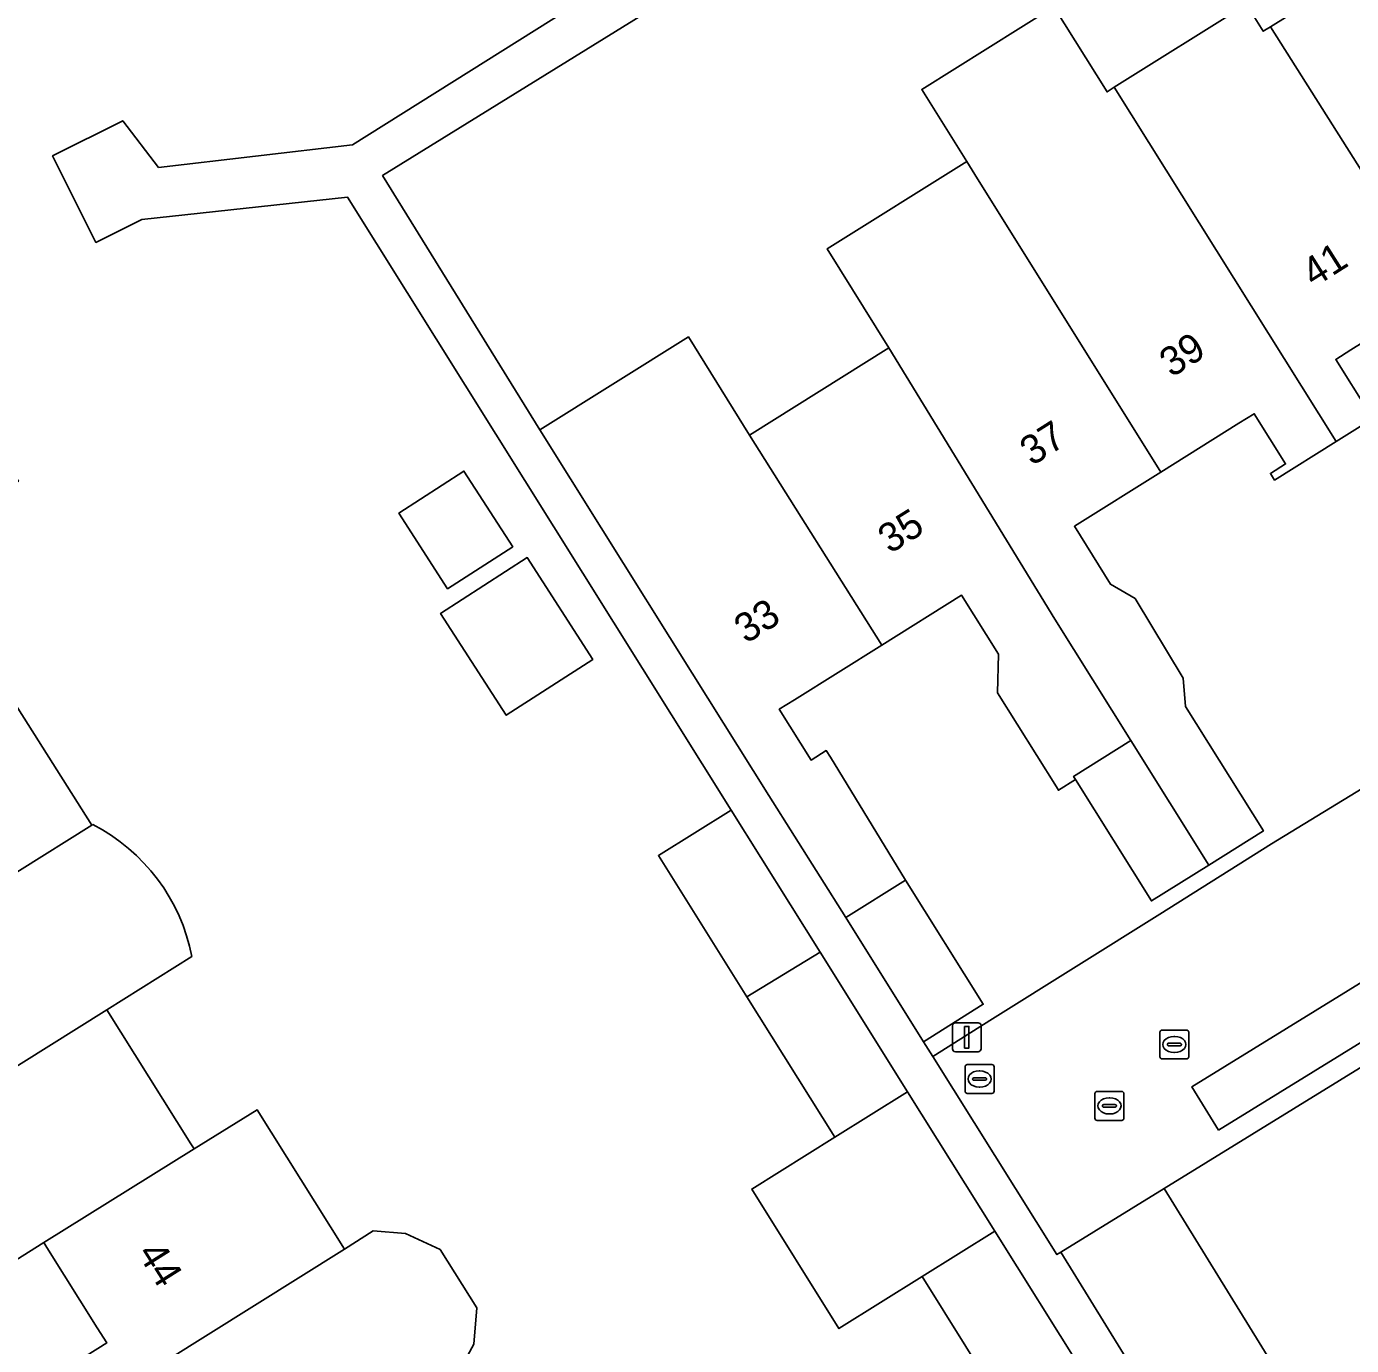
# Model space of a CAD drawing. Extents: x 157767 to 159172, y 387839 to 389425.
# Drawn here: x 158299.66 to 158345.52, y 388177.16 to 388222.82 of the extents above; entities that cross this region are included whole.
import ezdxf

# ---------------------------------------------------------------- set-up
doc = ezdxf.new("R2010")
doc.units = 0
for name, color, linetype in [('IMGEO_Brandkraan', 7, 'Continuous'), ('IMGEO_Erf', 7, 'Continuous'), ('IMGEO_Kolk', 7, 'Continuous'), ('IMGEO_Lichtmast', 7, 'Continuous'), ('IMGEO_Muur', 7, 'Continuous'), ('IMGEO_Pand', 7, 'Continuous'), ('IMGEO_Pand_nummerreeks', 7, 'Continuous'), ('IMGEO_Parkeervlak_open', 7, 'Continuous'), ('IMGEO_Rijbaan_lokaal_open', 7, 'Continuous'), ('IMGEO_Rioolput', 7, 'Continuous'), ('IMGEO_Voetpad_open', 7, 'Continuous')]:
    doc.layers.add(name, color=color, linetype=linetype)

msp = doc.modelspace()

# ---------------------------------------------------------------- linework, layer by layer
at = {"layer": 'IMGEO_Brandkraan'}
for p, q in [((158332.146, 388185.961), (158332.146, 388186.813)), ((158332.221, 388186.887), (158333.073, 388186.887)), ((158332.634, 388186.667), (158332.659, 388186.667)), ((158333.147, 388186.813), (158333.147, 388185.961)), ((158332.405, 388186.381), (158332.405, 388186.393)), ((158332.843, 388186.344), (158332.445, 388186.344)), ((158332.448, 388186.43), (158332.846, 388186.43)), ((158332.889, 388186.393), (158332.889, 388186.381)), ((158333.073, 388185.887), (158332.221, 388185.887)), ((158332.657, 388186.107), (158332.632, 388186.107))]:
    msp.add_line(p, q, dxfattribs=at)
for points in [[(158332.146, 388185.961), (158332.146, 388186.813)], [(158332.221, 388186.887), (158333.073, 388186.887)], [(158333.147, 388186.813), (158333.147, 388185.961)], [(158333.073, 388185.887), (158332.221, 388185.887)]]:
    msp.add_lwpolyline(points, dxfattribs=at)
for centre, radius, start, end in [((158332.223, 388186.811), 0.0765, 91.552, 178.448), ((158332.223, 388186.811), 0.0765, 91.552, 178.448), ((158333.071, 388186.811), 0.0765, 1.552, 88.448), ((158333.071, 388186.811), 0.0765, 1.552, 88.448), ((158332.445, 388186.39), 0.0403, 85.8775, 175.7526), ((158332.442, 388186.38), 0.0366, 178.938, 274.7102), ((158332.846, 388186.387), 0.043, 264.8664, 352.4533), ((158332.85, 388186.392), 0.0386, 1.7309, 96.639), ((158332.223, 388185.963), 0.0765, 181.552, 268.448), ((158332.223, 388185.963), 0.0765, 181.552, 268.448), ((158333.071, 388185.963), 0.0765, 271.552, 358.448), ((158333.071, 388185.963), 0.0765, 271.552, 358.448)]:
    msp.add_arc(centre, radius, start, end, dxfattribs=at)
for centre, major_axis, ratio, start_param, end_param in [((158332.633, 388186.387), (-0.387, 0.002), 0.722429, 4.712389, 7.853982), ((158332.658, 388186.387), (-0.39, 0.002), 0.717154, 1.570796, 4.712389)]:
    msp.add_ellipse(centre, major_axis=major_axis, ratio=ratio, start_param=start_param, end_param=end_param, dxfattribs=at)
at = {"layer": 'IMGEO_Erf'}
for points in [[(158352.638, 388149.483), (158342.348, 388166.462), (158339.829, 388164.885), (158336.71, 388169.869), (158333.687, 388174.698), (158330.654, 388179.545), (158327.78, 388177.748), (158324.761, 388182.578), (158327.632, 388184.373), (158324.594, 388189.227), (158321.531, 388194.121), (158324.05, 388195.698), (158310.772, 388216.911), (158303.653, 388216.141), (158302.062, 388215.346), (158300.563, 388218.345), (158302.989, 388219.558), (158304.231, 388217.941), (158310.937, 388218.725), (158339.805, 388236.853), (158338.261, 388239.455), (158339.941, 388240.451), (158341.485, 388237.85), (158354.972, 388246.308)], [(158352.633, 388242.812), (158311.985, 388217.662), (158317.43, 388208.862), (158322.569, 388212.076), (158324.68, 388208.678), (158329.51, 388211.699), (158327.369, 388215.123), (158332.203, 388218.146), (158330.642, 388220.645), (158335.214, 388223.501), (158337.058, 388220.56), (158337.309, 388220.717), (158341.89, 388223.582), (158342.466, 388222.66), (158342.715, 388222.816), (158347.548, 388225.838)], [(158288.882, 388228.585), (158287.241, 388221.328), (158285.582, 388213.989), (158285.537, 388213.792), (158285.678, 388213.567), (158287.513, 388214.764), (158290.986, 388215.147), (158292.361, 388212.95), (158293.959, 388210.397), (158296.356, 388211.9), (158299.38, 388207.078), (158296.984, 388205.563), (158295.817, 388204.825), (158298.865, 388200.005), (158301.921, 388195.173), (158301.957, 388195.196)], [(158348.581, 388213.55), (158345.5, 388211.624), (158344.976, 388211.296), (158346.113, 388209.477)], [(158346.781, 388209.576), (158344.993, 388208.458), (158342.854, 388207.12), (158342.711, 388207.349), (158343.237, 388207.678), (158342.15, 388209.416), (158341.624, 388209.087), (158338.92, 388207.396), (158335.927, 388205.524), (158337.182, 388203.516), (158338.026, 388203.018), (158339.693, 388200.264), (158339.772, 388199.287), (158342.47, 388194.973), (158340.58, 388193.791), (158338.596, 388192.55), (158335.966, 388196.755), (158335.373, 388196.384), (158335.303, 388196.496), (158333.262, 388199.758), (158333.301, 388201.09), (158332.025, 388203.131), (158329.261, 388201.403), (158326.24, 388199.514), (158325.715, 388199.186), (158326.814, 388197.429), (158327.339, 388197.757), (158327.482, 388197.528), (158330.086, 388193.272), (158332.774, 388188.973), (158330.703, 388187.677), (158331.025, 388187.169), (158333.092, 388188.466), (158338.88, 388192.098), (158342.746, 388194.533), (158348.606, 388198.107)], [(158305.387, 388190.624), (158302.443, 388188.781), (158305.35, 388184.137), (158305.458, 388183.964), (158307.641, 388185.324), (158310.661, 388180.499), (158311.663, 388181.126), (158312.771, 388181.044), (158313.976, 388180.48), (158315.241, 388178.461), (158315.14, 388177.208), (158314.617, 388176.244)], [(158300.695, 388176.163), (158302.435, 388177.252), (158302.107, 388177.777), (158300.366, 388180.558), (158300.261, 388180.726), (158298.305, 388179.507)]]:
    msp.add_lwpolyline(points, dxfattribs=at)
for points in [[(158312.546, 388205.978), (158314.8, 388207.43), (158316.488, 388204.812), (158314.234, 388203.359)], [(158316.261, 388198.98), (158313.991, 388202.504), (158316.989, 388204.436), (158319.259, 388200.912)], [(158365.167, 388198.706), (158352.615, 388190.965), (158339.034, 388182.597), (158342.746, 388176.574), (158344.937, 388173.02), (158341.361, 388170.817), (158342.735, 388168.588), (158345.292, 388170.164), (158347.446, 388166.668), (158349.073, 388167.671), (158351.12, 388164.35), (158349.493, 388163.347), (158350.241, 388162.135), (158353.069, 388157.546), (158355.265, 388158.899), (158357.294, 388155.608), (158355.098, 388154.254), (158355.258, 388153.995), (158352.825, 388152.496), (158354.129, 388150.416), (158383.764, 388168.963), (158383.379, 388169.579), (158381.815, 388172.081)]]:
    msp.add_lwpolyline(points, close=True, dxfattribs=at)
msp.add_arc((158298.947, 388189.365), 6.562, 11.0598, 62.6961, dxfattribs=at)
at = {"layer": 'IMGEO_Kolk'}
for p, q in [((158338.887, 388187.156), (158338.887, 388188.008)), ((158338.962, 388188.082), (158339.814, 388188.082)), ((158339.888, 388188.008), (158339.888, 388187.156)), ((158339.146, 388187.576), (158339.146, 388187.588)), ((158339.584, 388187.539), (158339.186, 388187.539)), ((158339.189, 388187.625), (158339.587, 388187.625)), ((158339.375, 388187.862), (158339.4, 388187.862)), ((158339.63, 388187.588), (158339.63, 388187.576)), ((158339.814, 388187.082), (158338.962, 388187.082)), ((158339.398, 388187.302), (158339.373, 388187.302))]:
    msp.add_line(p, q, dxfattribs=at)
for points in [[(158338.887, 388187.156), (158338.887, 388188.008)], [(158338.962, 388188.082), (158339.814, 388188.082)], [(158339.888, 388188.008), (158339.888, 388187.156)], [(158339.814, 388187.082), (158338.962, 388187.082)]]:
    msp.add_lwpolyline(points, dxfattribs=at)
for centre, radius, start, end in [((158338.964, 388188.006), 0.0765, 91.552, 178.448), ((158338.964, 388188.006), 0.0765, 91.552, 178.448), ((158339.812, 388188.006), 0.0765, 1.552, 88.448), ((158339.812, 388188.006), 0.0765, 1.552, 88.448), ((158339.186, 388187.585), 0.0403, 85.8775, 175.7526), ((158339.183, 388187.575), 0.0366, 178.938, 274.7102), ((158339.587, 388187.582), 0.043, 264.8664, 352.4533), ((158339.591, 388187.587), 0.0386, 1.7309, 96.639), ((158338.964, 388187.158), 0.0765, 181.552, 268.448), ((158338.964, 388187.158), 0.0765, 181.552, 268.448), ((158339.812, 388187.158), 0.0765, 271.552, 358.448), ((158339.812, 388187.158), 0.0765, 271.552, 358.448)]:
    msp.add_arc(centre, radius, start, end, dxfattribs=at)
for centre, major_axis, ratio, start_param, end_param in [((158339.374, 388187.582), (-0.387, 0.002), 0.722429, 4.712389, 7.853982), ((158339.399, 388187.582), (-0.39, 0.002), 0.717154, 1.570796, 4.712389)]:
    msp.add_ellipse(centre, major_axis=major_axis, ratio=ratio, start_param=start_param, end_param=end_param, dxfattribs=at)
at = {"layer": 'IMGEO_Lichtmast'}
for p, q in [((158331.708, 388187.433), (158331.708, 388188.233)), ((158331.708, 388188.233), (158331.708, 388187.433)), ((158331.808, 388188.333), (158332.598, 388188.333)), ((158332.598, 388188.333), (158331.808, 388188.333)), ((158332.698, 388188.233), (158332.698, 388187.433)), ((158332.698, 388187.433), (158332.698, 388188.233)), ((158332.598, 388187.333), (158331.808, 388187.333)), ((158331.808, 388187.333), (158332.598, 388187.333))]:
    msp.add_line(p, q, dxfattribs=at)
msp.add_lwpolyline([(158332.128, 388188.208), (158332.278, 388188.208), (158332.278, 388187.458), (158332.128, 388187.458), (158332.128, 388188.208)], dxfattribs=at)
for centre, start, end in [((158331.808, 388188.233), 90, 180), ((158331.808, 388188.233), 90, 180), ((158332.598, 388188.233), 0, 90), ((158332.598, 388188.233), 360, 90), ((158331.808, 388187.433), 180, 270), ((158331.808, 388187.433), 180, 270), ((158332.598, 388187.433), 270, 0), ((158332.598, 388187.433), 270, 0)]:
    msp.add_arc(centre, 0.1, start, end, dxfattribs=at)
at = {"layer": 'IMGEO_Muur'}
msp.add_lwpolyline([(158352.615, 388190.965), (158339.034, 388182.597)], dxfattribs=at)
at = {"layer": 'IMGEO_Pand'}
for points in [[(158352.186, 388218.514), (158347.548, 388225.838), (158342.715, 388222.816), (158348.581, 388213.55), (158350.352, 388214.658), (158350.209, 388214.887), (158349.684, 388214.559), (158348.609, 388216.277), (158349.134, 388216.605)], [(158337.309, 388220.717), (158337.058, 388220.56), (158335.214, 388223.501), (158330.642, 388220.645), (158332.203, 388218.146), (158332.484, 388217.7), (158338.92, 388207.396), (158341.624, 388209.087), (158342.15, 388209.416), (158343.237, 388207.678), (158342.711, 388207.349), (158342.854, 388207.12), (158344.993, 388208.458)], [(158337.309, 388220.717), (158344.993, 388208.458), (158346.781, 388209.576), (158346.638, 388209.805), (158346.113, 388209.477), (158344.976, 388211.296), (158345.5, 388211.624), (158348.581, 388213.55), (158342.715, 388222.816), (158342.466, 388222.66), (158341.89, 388223.582)], [(158338.92, 388207.396), (158332.484, 388217.7), (158332.203, 388218.146), (158327.369, 388215.123), (158329.51, 388211.699), (158335.252, 388202.31), (158337.882, 388198.105), (158340.58, 388193.791), (158342.47, 388194.973), (158339.772, 388199.287), (158339.693, 388200.264), (158338.026, 388203.018), (158337.182, 388203.516), (158335.927, 388205.524)], [(158328.015, 388191.977), (158330.086, 388193.272), (158327.482, 388197.528), (158327.339, 388197.757), (158326.814, 388197.429), (158325.715, 388199.186), (158326.24, 388199.514), (158329.261, 388201.403), (158324.68, 388208.678), (158322.569, 388212.076), (158317.43, 388208.862), (158319.551, 388205.471), (158322.7, 388200.436), (158325.351, 388196.196)], [(158324.68, 388208.678), (158329.261, 388201.403), (158332.025, 388203.131), (158333.301, 388201.09), (158333.262, 388199.758), (158335.303, 388196.496), (158335.373, 388196.384), (158335.966, 388196.755), (158335.898, 388196.864), (158337.882, 388198.105), (158335.252, 388202.31), (158329.51, 388211.699)], [(158316.488, 388204.812), (158314.8, 388207.43), (158312.546, 388205.978), (158314.234, 388203.359)], [(158319.259, 388200.912), (158316.989, 388204.436), (158313.991, 388202.504), (158316.261, 388198.98)], [(158299.421, 388193.609), (158301.921, 388195.173), (158298.865, 388200.005), (158296.392, 388198.45), (158282.82, 388189.919), (158283.973, 388188.076), (158288.449, 388190.878), (158288.121, 388191.404), (158289.916, 388192.527), (158290.245, 388192.002), (158292.107, 388189.027)], [(158335.966, 388196.755), (158338.596, 388192.55), (158340.58, 388193.791), (158337.882, 388198.105), (158335.898, 388196.864)], [(158327.127, 388190.782), (158324.05, 388195.698), (158321.531, 388194.121), (158324.594, 388189.227)], [(158328.015, 388191.977), (158330.703, 388187.677), (158332.774, 388188.973), (158330.086, 388193.272)], [(158330.152, 388185.948), (158327.127, 388190.782), (158324.594, 388189.227), (158327.632, 388184.373)], [(158305.458, 388183.964), (158305.35, 388184.137), (158302.443, 388188.781), (158288.839, 388180.263), (158290.058, 388178.315), (158294.534, 388181.117), (158294.206, 388181.643), (158295.961, 388182.741), (158296.29, 388182.216), (158298.183, 388179.192), (158298.412, 388179.335), (158298.305, 388179.507), (158300.261, 388180.726)], [(158330.152, 388185.948), (158327.632, 388184.373), (158324.761, 388182.578), (158327.78, 388177.748), (158330.654, 388179.545), (158333.174, 388181.121)], [(158310.661, 388180.499), (158307.641, 388185.324), (158305.458, 388183.964), (158300.261, 388180.726), (158300.366, 388180.558), (158302.107, 388177.777), (158302.435, 388177.252), (158300.695, 388176.163), (158300.366, 388176.687), (158300.137, 388176.544), (158301.323, 388174.65)], [(158342.746, 388176.574), (158339.034, 388182.597), (158335.458, 388180.394), (158339.187, 388174.344)], [(158313.689, 388175.662), (158314.617, 388176.244), (158315.14, 388177.208), (158315.241, 388178.461), (158313.976, 388180.48), (158312.771, 388181.044), (158311.663, 388181.126), (158310.661, 388180.499), (158301.323, 388174.65), (158302.563, 388172.668), (158302.792, 388172.812), (158302.464, 388173.338), (158304.215, 388174.434), (158304.546, 388173.91), (158306.343, 388171.059)], [(158333.174, 388181.121), (158330.654, 388179.545), (158333.687, 388174.698), (158336.208, 388176.272)]]:
    msp.add_lwpolyline(points, close=True, dxfattribs=at)
for points in [[(158301.957, 388195.196), (158301.921, 388195.173), (158299.421, 388193.609), (158292.107, 388189.027), (158293.851, 388186.24), (158294.18, 388185.715), (158292.367, 388184.581), (158292.038, 388185.106), (158287.562, 388182.304), (158288.839, 388180.263), (158302.443, 388188.781)], [(158302.443, 388188.781), (158305.387, 388190.624)]]:
    msp.add_lwpolyline(points, dxfattribs=at)
msp.add_arc((158298.947, 388189.365), 6.562, 11.0598, 62.6961, dxfattribs=at)
at = {"layer": 'IMGEO_Parkeervlak_open'}
msp.add_lwpolyline([(158340.911, 388184.618), (158361.412, 388197.254), (158360.492, 388198.747), (158339.992, 388186.111)], close=True, dxfattribs=at)
at = {"layer": 'IMGEO_Rijbaan_lokaal_open'}
msp.add_lwpolyline([(158340.911, 388184.618), (158339.992, 388186.111), (158360.492, 388198.747), (158361.412, 388197.254)], close=True, dxfattribs=at)
msp.add_lwpolyline([(158348.606, 388198.107), (158342.746, 388194.533), (158338.88, 388192.098), (158333.092, 388188.466), (158331.025, 388187.169), (158335.32, 388180.308), (158335.458, 388180.394), (158339.034, 388182.597), (158352.615, 388190.965)], dxfattribs=at)
at = {"layer": 'IMGEO_Rioolput'}
for p, q in [((158336.64, 388185.03), (158336.64, 388185.882)), ((158336.715, 388185.956), (158337.567, 388185.956)), ((158337.128, 388185.736), (158337.153, 388185.736)), ((158337.641, 388185.882), (158337.641, 388185.03)), ((158336.899, 388185.45), (158336.899, 388185.462)), ((158337.337, 388185.413), (158336.939, 388185.413)), ((158336.942, 388185.499), (158337.34, 388185.499)), ((158337.383, 388185.462), (158337.383, 388185.45)), ((158337.567, 388184.956), (158336.715, 388184.956)), ((158337.151, 388185.176), (158337.126, 388185.176))]:
    msp.add_line(p, q, dxfattribs=at)
for points in [[(158336.64, 388185.03), (158336.64, 388185.882)], [(158336.715, 388185.956), (158337.567, 388185.956)], [(158337.641, 388185.882), (158337.641, 388185.03)], [(158337.567, 388184.956), (158336.715, 388184.956)]]:
    msp.add_lwpolyline(points, dxfattribs=at)
for centre, radius, start, end in [((158336.717, 388185.88), 0.0765, 91.552, 178.448), ((158336.717, 388185.88), 0.0765, 91.552, 178.448), ((158337.565, 388185.88), 0.0765, 1.552, 88.448), ((158337.565, 388185.88), 0.0765, 1.552, 88.448), ((158336.939, 388185.459), 0.0403, 85.8775, 175.7526), ((158336.936, 388185.449), 0.0366, 178.938, 274.7102), ((158337.34, 388185.456), 0.043, 264.8664, 352.4533), ((158337.344, 388185.461), 0.0386, 1.7309, 96.639), ((158336.717, 388185.032), 0.0765, 181.552, 268.448), ((158336.717, 388185.032), 0.0765, 181.552, 268.448), ((158337.565, 388185.032), 0.0765, 271.552, 358.448), ((158337.565, 388185.032), 0.0765, 271.552, 358.448)]:
    msp.add_arc(centre, radius, start, end, dxfattribs=at)
for centre, major_axis, ratio, start_param, end_param in [((158337.127, 388185.456), (-0.387, 0.002), 0.722429, 4.712389, 7.853982), ((158337.152, 388185.456), (-0.39, 0.002), 0.717154, 1.570796, 4.712389)]:
    msp.add_ellipse(centre, major_axis=major_axis, ratio=ratio, start_param=start_param, end_param=end_param, dxfattribs=at)
at = {"layer": 'IMGEO_Voetpad_open'}
for points in [[(158354.972, 388246.308), (158341.485, 388237.85), (158339.805, 388236.853), (158310.937, 388218.725), (158304.231, 388217.941), (158302.989, 388219.558), (158300.563, 388218.345), (158302.062, 388215.346), (158303.653, 388216.141), (158310.772, 388216.911), (158324.05, 388195.698), (158327.127, 388190.782), (158330.152, 388185.948), (158333.174, 388181.121), (158336.208, 388176.272), (158339.23, 388171.444), (158342.348, 388166.462), (158352.638, 388149.483)], [(158347.695, 388160.541), (158344.889, 388165.093), (158342.735, 388168.588), (158341.361, 388170.817), (158339.187, 388174.344), (158335.458, 388180.394), (158335.32, 388180.308), (158331.025, 388187.169), (158330.703, 388187.677), (158328.015, 388191.977), (158325.351, 388196.196), (158322.7, 388200.436), (158319.551, 388205.471), (158317.43, 388208.862), (158311.985, 388217.662), (158352.633, 388242.812)]]:
    msp.add_lwpolyline(points, dxfattribs=at)

# ---------------------------------------------------------------- texts
at = {"layer": 'IMGEO_Pand_nummerreeks'}
for s, rotation, p in [('41', 32.341, (158344.215, 388213.768)), ('39', 32.3435, (158339.289, 388210.651)), ('37', 32.341, (158334.459, 388207.591)), ('35', 32.0144, (158329.542, 388204.551)), ('33', 32.0144, (158324.563, 388201.438)), ('44', 302.1943, (158303.473, 388180.354))]:
    msp.add_text(s, height=1, rotation=rotation, dxfattribs=at).set_placement(p)

doc.saveas('drawing.dxf')
